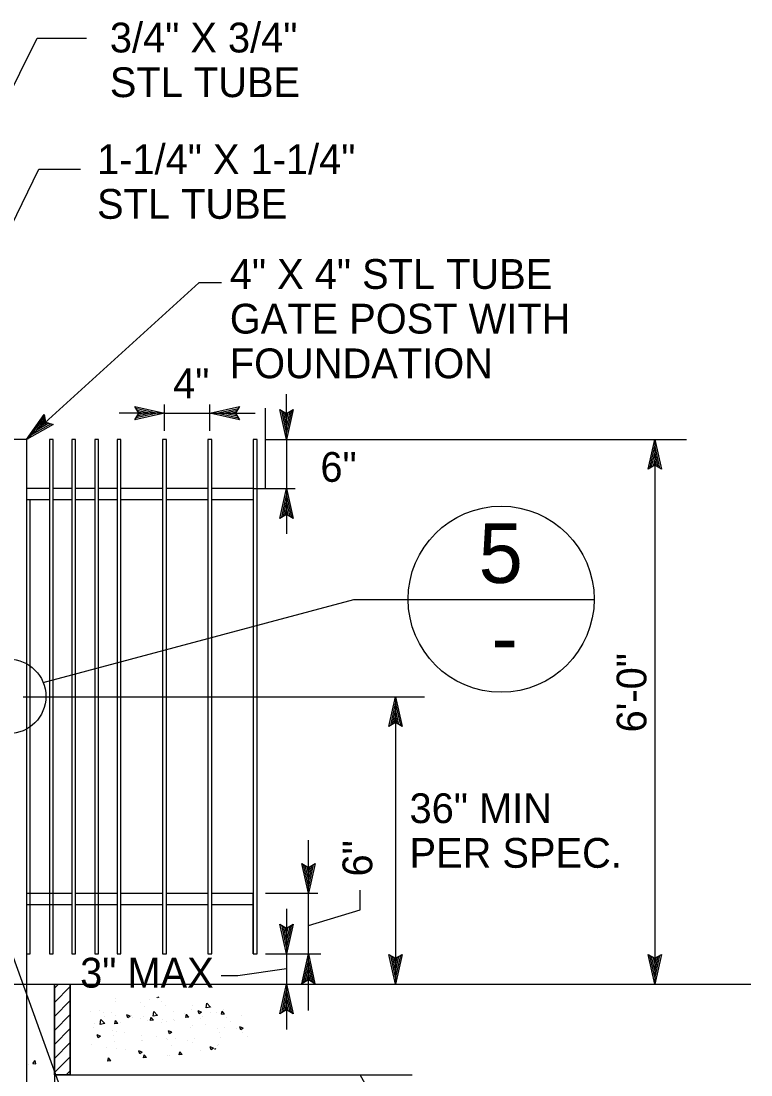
# Model space of a CAD drawing. Extents: x 6710407 to 6714861, y 1868090 to 1871317.
# Drawn here: x 6712218.2 to 6712365.4, y 1869755 to 1869967.3 of the extents above; entities that cross this region are included whole.
import ezdxf

# ---------------------------------------------------------------- set-up
doc = ezdxf.new("R2010")
doc.units = 0
for name, color, linetype in [('Erosion C (Lv35)', 7, 'Continuous'), ('G-MARK', 7, 'Continuous'), ('G-TEXT', 7, 'Continuous'), ('Nongeo Data(60)', 7, 'Continuous')]:
    doc.layers.add(name, color=color, linetype=linetype)

# ---------------------------------------------------------------- blocks, each defined once
blk = doc.blocks.new('SC8415')
at = {"layer": 'Erosion C (Lv35)'}
for p, q in [((-1.69662, 1.7688), (-1.69662, 1.7688)), ((-1.69606, 1.76963), (-1.69579, 1.76945)), ((-1.69579, 1.76945), (-1.69573, 1.76963)), ((-1.69408, 1.76913), (-1.69408, 1.76913)), ((-1.68715, 1.76926), (-1.68715, 1.76926)), ((-1.70955, 1.76614), (-1.70906, 1.76672)), ((-1.70943, 1.76711), (-1.70943, 1.76711)), ((-1.70894, 1.76609), (-1.70906, 1.76672)), ((-1.70689, 1.76745), (-1.70689, 1.76745)), ((-1.70669, 1.76754), (-1.7059, 1.76836)), ((-1.70669, 1.76754), (-1.70579, 1.7674)), ((-1.70579, 1.7674), (-1.7059, 1.76836)), ((-1.70484, 1.76651), (-1.70412, 1.76679)), ((-1.70433, 1.76617), (-1.70412, 1.76679)), ((-1.70304, 1.76795), (-1.70304, 1.76795)), ((-1.70278, 1.76714), (-1.70278, 1.76714)), ((-1.69901, 1.76659), (-1.69901, 1.76659)), ((-1.6975, 1.7679), (-1.6975, 1.7679)), ((-1.69585, 1.76586), (-1.69506, 1.76668)), ((-1.69494, 1.76572), (-1.69506, 1.76668)), ((-1.69309, 1.7676), (-1.69309, 1.7676)), ((-1.69228, 1.76861), (-1.69228, 1.76861)), ((-1.68716, 1.76862), (-1.68716, 1.76862)), ((-1.68394, 1.76681), (-1.68394, 1.76681)), ((-1.682, 1.76664), (-1.682, 1.76664)), ((-1.71312, 1.76577), (-1.71312, 1.76577)), ((-1.71086, 1.76455), (-1.71086, 1.76455)), ((-1.71, 1.76543), (-1.71, 1.76543)), ((-1.70955, 1.76614), (-1.70894, 1.76608)), ((-1.70791, 1.76649), (-1.70791, 1.76649)), ((-1.70672, 1.76656), (-1.70672, 1.76656)), ((-1.70494, 1.76557), (-1.70494, 1.76557)), ((-1.70484, 1.76651), (-1.70433, 1.76617)), ((-1.70458, 1.7652), (-1.70458, 1.7652)), ((-1.70226, 1.7655), (-1.70177, 1.76608)), ((-1.70226, 1.7655), (-1.70165, 1.76545)), ((-1.70165, 1.76545), (-1.70177, 1.76609)), ((-1.7013, 1.76633), (-1.7013, 1.76633)), ((-1.6993, 1.76479), (-1.6993, 1.76479)), ((-1.69916, 1.76497), (-1.69916, 1.76497)), ((-1.69762, 1.76452), (-1.69762, 1.76452)), ((-1.69675, 1.76513), (-1.69675, 1.76513)), ((-1.69588, 1.7661), (-1.69588, 1.7661)), ((-1.69585, 1.76586), (-1.69494, 1.76572)), ((-1.69497, 1.76486), (-1.69449, 1.76545)), ((-1.69497, 1.76486), (-1.69437, 1.76481)), ((-1.69437, 1.76481), (-1.69448, 1.76545)), ((-1.69373, 1.76474), (-1.69373, 1.76474)), ((-1.6929, 1.76563), (-1.6929, 1.76563)), ((-1.69241, 1.76523), (-1.69241, 1.76523)), ((-1.69065, 1.76537), (-1.69065, 1.76537)), ((-1.69045, 1.76587), (-1.69045, 1.76587)), ((-1.69023, 1.7657), (-1.68952, 1.76597)), ((-1.69023, 1.7657), (-1.68973, 1.76536)), ((-1.68973, 1.76536), (-1.68952, 1.76597)), ((-1.68831, 1.76451), (-1.68831, 1.76451)), ((-1.68769, 1.76423), (-1.6872, 1.76481)), ((-1.68727, 1.76588), (-1.68727, 1.76588)), ((-1.68708, 1.76417), (-1.6872, 1.76481)), ((-1.68649, 1.76648), (-1.68649, 1.76648)), ((-1.68503, 1.76565), (-1.68503, 1.76565)), ((-1.685, 1.76418), (-1.68421, 1.765)), ((-1.68473, 1.76639), (-1.68473, 1.76639)), ((-1.6841, 1.76404), (-1.68421, 1.765)), ((-1.71337, 1.76324), (-1.71266, 1.76351)), ((-1.71337, 1.76324), (-1.71287, 1.7629)), ((-1.71325, 1.76239), (-1.71325, 1.76239)), ((-1.71287, 1.7629), (-1.71266, 1.76351)), ((-1.7121, 1.7631), (-1.7121, 1.7631)), ((-1.70956, 1.76344), (-1.70956, 1.76344)), ((-1.70843, 1.76232), (-1.70843, 1.76232)), ((-1.70803, 1.7631), (-1.70803, 1.7631)), ((-1.70571, 1.76395), (-1.70571, 1.76395)), ((-1.7029, 1.76375), (-1.7029, 1.76375)), ((-1.7025, 1.76334), (-1.7025, 1.76334)), ((-1.69877, 1.76242), (-1.69806, 1.7627)), ((-1.69877, 1.76242), (-1.69827, 1.76208)), ((-1.69826, 1.76208), (-1.69806, 1.7627)), ((-1.69658, 1.76435), (-1.69658, 1.76435)), ((-1.68916, 1.76247), (-1.68916, 1.76247)), ((-1.68769, 1.76423), (-1.68708, 1.76417)), ((-1.6874, 1.7625), (-1.6874, 1.7625)), ((-1.68662, 1.7628), (-1.68662, 1.7628)), ((-1.685, 1.76418), (-1.6841, 1.76404)), ((-1.68289, 1.76428), (-1.68289, 1.76428)), ((-1.68277, 1.76331), (-1.68277, 1.76331)), ((-1.71417, 1.76163), (-1.71417, 1.76163)), ((-1.70874, 1.7614), (-1.70874, 1.7614)), ((-1.70332, 1.76117), (-1.70332, 1.76117)), ((-1.70302, 1.76037), (-1.70302, 1.76037)), ((-1.70197, 1.76078), (-1.70197, 1.76078)), ((-1.69943, 1.76112), (-1.69943, 1.76112)), ((-1.6979, 1.76094), (-1.6979, 1.76094)), ((-1.69775, 1.76113), (-1.69775, 1.76113)), ((-1.69558, 1.76162), (-1.69558, 1.76162)), ((-1.6927, 1.7608), (-1.6927, 1.7608)), ((-1.69253, 1.76185), (-1.69253, 1.76185)), ((-1.69247, 1.76071), (-1.69247, 1.76071)), ((-1.68705, 1.76048), (-1.68705, 1.76048)), ((-1.68677, 1.76182), (-1.68677, 1.76182)), ((-1.68417, 1.76161), (-1.68346, 1.76188)), ((-1.68417, 1.76161), (-1.68366, 1.76127)), ((-1.68366, 1.76127), (-1.68346, 1.76188)), ((-1.70839, 1.75994), (-1.70839, 1.75994)), ((-1.70815, 1.75972), (-1.70815, 1.75972)), ((-1.70775, 1.75896), (-1.70765, 1.75908)), ((-1.70762, 1.7589), (-1.70765, 1.75908)), ((-1.70731, 1.75915), (-1.7066, 1.75942)), ((-1.70731, 1.75915), (-1.7068, 1.75881)), ((-1.7068, 1.75881), (-1.7066, 1.75942)), ((-1.70455, 1.75876), (-1.70455, 1.75876)), ((-1.70085, 1.75786), (-1.70036, 1.75844)), ((-1.70024, 1.75781), (-1.70036, 1.75844)), ((-1.69862, 1.75978), (-1.69862, 1.75978)), ((-1.69271, 1.75833), (-1.692, 1.75861)), ((-1.69271, 1.75833), (-1.6922, 1.75799)), ((-1.69265, 1.75847), (-1.69265, 1.75847)), ((-1.6922, 1.75799), (-1.69199, 1.75861)), ((-1.69183, 1.75846), (-1.69183, 1.75846)), ((-1.68929, 1.7588), (-1.68929, 1.7588)), ((-1.68752, 1.75912), (-1.68752, 1.75912)), ((-1.68544, 1.7593), (-1.68544, 1.7593)), ((-1.68224, 1.75988), (-1.68224, 1.75988)), ((-1.70085, 1.75786), (-1.70025, 1.7578)), ((-1.69825, 1.75762), (-1.69825, 1.75762)), ((-1.69787, 1.75775), (-1.69787, 1.75775)), ((-1.69357, 1.75722), (-1.69308, 1.7578)), ((-1.69357, 1.75722), (-1.69296, 1.75717)), ((-1.69296, 1.75717), (-1.69307, 1.75781)), ((-1.68628, 1.75658), (-1.68579, 1.75717)), ((-1.68628, 1.75658), (-1.68567, 1.75653)), ((-1.68567, 1.75653), (-1.68579, 1.75717))]:
    blk.add_line(p, q, dxfattribs=at)

msp = doc.modelspace()

# ---------------------------------------------------------------- linework, layer by layer
at = {"layer": 'G-MARK'}
for p, q in [((6712221.51, 1869963.85), (6712231.4, 1869963.85)), ((6712221.81, 1869937.43), (6712230.24, 1869937.43)), ((6712271.76, 1869882.98), (6712271.76, 1869892.12)), ((6712247.15, 1869884.69), (6712247.15, 1869889.99)), ((6712256.29, 1869884.69), (6712256.29, 1869889.99)), ((6712247.15, 1869888.27), (6712238, 1869888.27)), ((6712247.15, 1869888.27), (6712256.29, 1869888.27)), ((6712256.29, 1869888.27), (6712265.43, 1869888.27)), ((6712267.53, 1869882.98), (6712352.35, 1869882.98)), ((6712267.53, 1869882.98), (6712273.48, 1869882.98)), ((6712271.76, 1869882.98), (6712271.76, 1869873.07)), ((6712345.98, 1869882.98), (6712345.98, 1869773.25)), ((6712271.76, 1869873.07), (6712271.76, 1869863.93)), ((6712222.72, 1869833.99), (6712285.31, 1869850.71)), ((6712285.31, 1869850.71), (6712296.07, 1869850.74)), ((6712218.67, 1869831.16), (6712299.57, 1869831.16)), ((6712293.73, 1869831.16), (6712293.73, 1869773.25)), ((6712234.89, 1869728.28), (6712198.51, 1869828.82)), ((6712276.16, 1869767.91), (6712276.16, 1869802.24)), ((6712286.57, 1869788.2), (6712286.57, 1869792.19)), ((6712267.53, 1869791.55), (6712278.05, 1869791.55)), ((6712271.76, 1869788.41), (6712271.76, 1869773.25)), ((6712276.16, 1869785.08), (6712286.57, 1869788.2)), ((6712267.53, 1869779.34), (6712278.68, 1869779.34)), ((6712271.76, 1869776.3), (6712261.95, 1869774.95)), ((6712261.95, 1869774.95), (6712258.56, 1869774.95)), ((6712271.76, 1869773.25), (6712271.76, 1869764.1)), ((6712292.64, 1869744.38), (6712286.57, 1869754.96))]:
    msp.add_line(p, q, dxfattribs=at)
for points in [[(6712179.33, 1869878.93), (6712221.51, 1869963.85), (6712221.51, 1869963.85)], [(6712190.63, 1869873.39), (6712221.81, 1869937.43)], [(6712258.62, 1869914.56), (6712254.1, 1869914.56), (6712219.34, 1869882.98)]]:
    msp.add_lwpolyline(points, dxfattribs=at)
at = {"layer": 'G-TEXT'}
for p, q in [((6712219.34, 1869882.98), (6712222.89, 1869888)), ((6712220.37, 1869883.92), (6712222.95, 1869887.58)), ((6712222.89, 1869888), (6712222.89, 1869888)), ((6712222.89, 1869888), (6712223.19, 1869886.48)), ((6712241.95, 1869888.27), (6712241.15, 1869889.61)), ((6712241.15, 1869889.61), (6712241.15, 1869889.61)), ((6712241.15, 1869889.61), (6712247.15, 1869888.27)), ((6712247.15, 1869888.27), (6712241.15, 1869886.94)), ((6712241.15, 1869886.94), (6712241.95, 1869888.27)), ((6712241.36, 1869889.25), (6712245.77, 1869888.27)), ((6712245.75, 1869888.27), (6712241.38, 1869887.3)), ((6712244.38, 1869888.27), (6712241.56, 1869887.65)), ((6712241.6, 1869888.9), (6712244.38, 1869888.27)), ((6712241.77, 1869888.55), (6712243, 1869888.27)), ((6712243, 1869888.27), (6712241.79, 1869888.01)), ((6712247.15, 1869888.27), (6712247.15, 1869888.27)), ((6712256.29, 1869888.27), (6712262.29, 1869889.6)), ((6712262.29, 1869886.93), (6712256.29, 1869888.27)), ((6712256.29, 1869888.27), (6712256.29, 1869888.27)), ((6712262.07, 1869887.29), (6712257.67, 1869888.27)), ((6712257.68, 1869888.27), (6712262.05, 1869889.24)), ((6712259.05, 1869888.27), (6712261.88, 1869888.89)), ((6712261.84, 1869887.65), (6712259.05, 1869888.27)), ((6712260.43, 1869888.27), (6712261.64, 1869888.54)), ((6712261.66, 1869887.99), (6712260.43, 1869888.27)), ((6712262.29, 1869889.6), (6712261.49, 1869888.27)), ((6712261.49, 1869888.27), (6712262.29, 1869886.93)), ((6712262.29, 1869889.6), (6712262.29, 1869889.6)), ((6712271.76, 1869882.98), (6712270.43, 1869888.98)), ((6712270.43, 1869888.98), (6712270.43, 1869888.98)), ((6712270.43, 1869888.98), (6712271.76, 1869888.18)), ((6712271.76, 1869884.37), (6712270.79, 1869888.74)), ((6712271.77, 1869885.74), (6712271.14, 1869888.56)), ((6712271.77, 1869887.12), (6712271.5, 1869888.33)), ((6712271.76, 1869888.18), (6712273.1, 1869888.98)), ((6712273.1, 1869888.98), (6712271.76, 1869882.98)), ((6712272.75, 1869888.76), (6712271.76, 1869884.35)), ((6712272.39, 1869888.52), (6712271.77, 1869885.74)), ((6712272.04, 1869888.35), (6712271.77, 1869887.12)), ((6712273.1, 1869888.98), (6712273.1, 1869888.98)), ((6712224.68, 1869886.02), (6712219.34, 1869882.98)), ((6712224.28, 1869886.14), (6712220.36, 1869883.91)), ((6712221.39, 1869884.84), (6712223.06, 1869887.2)), ((6712223.87, 1869886.25), (6712221.39, 1869884.84)), ((6712222.41, 1869885.77), (6712223.12, 1869886.78)), ((6712223.5, 1869886.39), (6712222.41, 1869885.77)), ((6712223.19, 1869886.48), (6712224.68, 1869886.02)), ((6712224.68, 1869886.02), (6712224.68, 1869886.02)), ((6712241.15, 1869886.94), (6712241.15, 1869886.94)), ((6712262.29, 1869886.93), (6712262.29, 1869886.93)), ((6712219.34, 1869882.98), (6712219.34, 1869882.98)), ((6712271.76, 1869882.98), (6712271.76, 1869882.98)), ((6712344.64, 1869876.98), (6712345.98, 1869882.98)), ((6712345, 1869877.19), (6712345.98, 1869881.6)), ((6712345.98, 1869882.98), (6712345.98, 1869882.98)), ((6712345.98, 1869882.98), (6712347.31, 1869876.97)), ((6712345.99, 1869881.58), (6712346.95, 1869877.21)), ((6712345.36, 1869877.43), (6712345.98, 1869880.21)), ((6712345.98, 1869880.21), (6712346.61, 1869877.39)), ((6712345.98, 1869877.78), (6712344.64, 1869876.98)), ((6712344.64, 1869876.98), (6712344.64, 1869876.98)), ((6712345.7, 1869877.6), (6712345.98, 1869878.83)), ((6712345.98, 1869878.83), (6712346.25, 1869877.62)), ((6712347.31, 1869876.98), (6712345.98, 1869877.78)), ((6712347.31, 1869876.98), (6712347.31, 1869876.98)), ((6712270.42, 1869867.07), (6712271.76, 1869873.07)), ((6712271.76, 1869873.07), (6712271.76, 1869873.07)), ((6712271.76, 1869873.07), (6712273.09, 1869867.07)), ((6712270.78, 1869867.29), (6712271.76, 1869871.69)), ((6712271.77, 1869871.68), (6712272.73, 1869867.3)), ((6712271.14, 1869867.52), (6712271.76, 1869870.31)), ((6712271.49, 1869867.7), (6712271.76, 1869868.92)), ((6712271.76, 1869870.31), (6712272.39, 1869867.48)), ((6712271.76, 1869868.92), (6712272.03, 1869867.72)), ((6712271.76, 1869867.87), (6712270.42, 1869867.07)), ((6712270.42, 1869867.07), (6712270.42, 1869867.07)), ((6712273.09, 1869867.07), (6712271.76, 1869867.87)), ((6712273.09, 1869867.07), (6712273.09, 1869867.07)), ((6712292.39, 1869825.16), (6712293.73, 1869831.16)), ((6712293.73, 1869831.16), (6712293.73, 1869831.16)), ((6712293.73, 1869831.16), (6712295.06, 1869825.16)), ((6712292.75, 1869825.38), (6712293.73, 1869829.78)), ((6712293.11, 1869825.61), (6712293.73, 1869828.4)), ((6712293.73, 1869829.77), (6712294.7, 1869825.39)), ((6712293.73, 1869828.4), (6712294.35, 1869825.57)), ((6712293.73, 1869825.96), (6712292.39, 1869825.16)), ((6712293.45, 1869825.79), (6712293.73, 1869827.01)), ((6712293.73, 1869827.01), (6712293.99, 1869825.81)), ((6712295.06, 1869825.16), (6712293.73, 1869825.96)), ((6712292.39, 1869825.16), (6712292.39, 1869825.16)), ((6712295.06, 1869825.16), (6712295.06, 1869825.16)), ((6712276.16, 1869791.55), (6712274.83, 1869797.55)), ((6712274.83, 1869797.55), (6712274.83, 1869797.55)), ((6712274.83, 1869797.55), (6712276.16, 1869796.75)), ((6712276.16, 1869792.94), (6712275.19, 1869797.32)), ((6712276.16, 1869794.32), (6712275.54, 1869797.14)), ((6712276.17, 1869795.7), (6712275.9, 1869796.91)), ((6712276.16, 1869796.75), (6712277.5, 1869797.55)), ((6712277.5, 1869797.55), (6712276.16, 1869791.55)), ((6712277.15, 1869797.34), (6712276.16, 1869792.93)), ((6712276.79, 1869797.1), (6712276.16, 1869794.32)), ((6712276.44, 1869796.93), (6712276.17, 1869795.7)), ((6712277.5, 1869797.55), (6712277.5, 1869797.55)), ((6712276.16, 1869791.55), (6712276.16, 1869791.55)), ((6712271.76, 1869779.34), (6712270.43, 1869785.34)), ((6712270.43, 1869785.34), (6712270.43, 1869785.34)), ((6712270.43, 1869785.34), (6712271.76, 1869784.54)), ((6712271.76, 1869780.73), (6712270.79, 1869785.11)), ((6712271.77, 1869782.11), (6712271.14, 1869784.93)), ((6712271.77, 1869783.49), (6712271.5, 1869784.7)), ((6712271.76, 1869784.54), (6712273.1, 1869785.34)), ((6712273.1, 1869785.34), (6712271.76, 1869779.34)), ((6712272.75, 1869785.13), (6712271.76, 1869780.72)), ((6712272.39, 1869784.89), (6712271.77, 1869782.11)), ((6712272.04, 1869784.72), (6712271.77, 1869783.49)), ((6712273.1, 1869785.34), (6712273.1, 1869785.34)), ((6712271.76, 1869779.34), (6712271.76, 1869779.34)), ((6712274.82, 1869773.34), (6712276.16, 1869779.34)), ((6712276.16, 1869779.34), (6712276.16, 1869779.34)), ((6712276.16, 1869779.34), (6712277.49, 1869773.34)), ((6712293.73, 1869773.25), (6712292.4, 1869779.25)), ((6712292.4, 1869779.25), (6712292.4, 1869779.25)), ((6712292.4, 1869779.25), (6712293.73, 1869778.45)), ((6712293.73, 1869778.45), (6712295.07, 1869779.25)), ((6712295.07, 1869779.25), (6712293.73, 1869773.25)), ((6712295.07, 1869779.25), (6712295.07, 1869779.25)), ((6712345.98, 1869773.25), (6712344.65, 1869779.25)), ((6712344.65, 1869779.25), (6712344.65, 1869779.25)), ((6712344.65, 1869779.25), (6712345.98, 1869778.45)), ((6712345.98, 1869778.45), (6712347.32, 1869779.25)), ((6712347.32, 1869779.25), (6712345.98, 1869773.25)), ((6712347.32, 1869779.25), (6712347.32, 1869779.25)), ((6712275.18, 1869773.56), (6712276.16, 1869777.96)), ((6712276.17, 1869777.95), (6712277.13, 1869773.58)), ((6712293.73, 1869774.64), (6712292.76, 1869779.01)), ((6712293.73, 1869776.01), (6712293.11, 1869778.83)), ((6712293.73, 1869777.39), (6712293.46, 1869778.6)), ((6712294.71, 1869779.03), (6712293.73, 1869774.63)), ((6712294.35, 1869778.8), (6712293.73, 1869776.01)), ((6712294.01, 1869778.62), (6712293.73, 1869777.39)), ((6712345.98, 1869774.64), (6712345.01, 1869779.01)), ((6712345.98, 1869776.01), (6712345.36, 1869778.83)), ((6712345.98, 1869777.39), (6712345.72, 1869778.6)), ((6712346.97, 1869779.03), (6712345.98, 1869774.63)), ((6712346.61, 1869778.8), (6712345.98, 1869776.01)), ((6712346.26, 1869778.62), (6712345.98, 1869777.39)), ((6712275.54, 1869773.79), (6712276.16, 1869776.58)), ((6712275.88, 1869773.97), (6712276.16, 1869775.2)), ((6712276.16, 1869776.58), (6712276.79, 1869773.76)), ((6712276.16, 1869775.2), (6712276.43, 1869773.99)), ((6712270.42, 1869767.25), (6712271.76, 1869773.25)), ((6712271.76, 1869773.25), (6712271.76, 1869773.25)), ((6712271.76, 1869773.25), (6712273.09, 1869767.25)), ((6712276.16, 1869774.14), (6712274.82, 1869773.34)), ((6712274.82, 1869773.34), (6712274.82, 1869773.34)), ((6712277.49, 1869773.34), (6712276.16, 1869774.14)), ((6712277.49, 1869773.34), (6712277.49, 1869773.34)), ((6712293.73, 1869773.25), (6712293.73, 1869773.25)), ((6712345.98, 1869773.25), (6712345.98, 1869773.25)), ((6712270.78, 1869767.46), (6712271.76, 1869771.87)), ((6712271.77, 1869771.86), (6712272.73, 1869767.48)), ((6712271.14, 1869767.7), (6712271.76, 1869770.48)), ((6712271.49, 1869767.87), (6712271.76, 1869769.1)), ((6712271.76, 1869770.48), (6712272.39, 1869767.66)), ((6712271.76, 1869769.1), (6712272.03, 1869767.89)), ((6712271.76, 1869768.05), (6712270.42, 1869767.25)), ((6712270.42, 1869767.25), (6712270.42, 1869767.25)), ((6712273.09, 1869767.25), (6712271.76, 1869768.05)), ((6712273.09, 1869767.25), (6712273.09, 1869767.25))]:
    msp.add_line(p, q, dxfattribs=at)
msp.add_lwpolyline([(6712219.34, 1869882.98), (6712219.33, 1869882.98), (6712219.34, 1869882.98)], close=True, dxfattribs=at)
at = {"layer": 'Nongeo Data(60)'}
for p, q in [((6712256.29, 1869888.27), (6712256.29, 1869888.27)), ((6712267.53, 1869873.07), (6712267.53, 1869889.25)), ((6712219.33, 1869882.98), (6712216.19, 1869882.98)), ((6712219.71, 1869882.98), (6712219.71, 1869882.98)), ((6712247.15, 1869882.98), (6712247.15, 1869882.98)), ((6712256.29, 1869882.98), (6712256.29, 1869882.98)), ((6712265.81, 1869882.98), (6712265.81, 1869882.98)), ((6712265.81, 1869874.78), (6712265.81, 1869874.78)), ((6712223.95, 1869873.07), (6712219.33, 1869873.07)), ((6712228.48, 1869873.07), (6712224.71, 1869873.07)), ((6712233.09, 1869873.07), (6712229.24, 1869873.07)), ((6712237.62, 1869873.07), (6712233.86, 1869873.07)), ((6712246.76, 1869873.07), (6712238.38, 1869873.07)), ((6712255.91, 1869873.07), (6712247.53, 1869873.07)), ((6712265.05, 1869873.07), (6712256.67, 1869873.07)), ((6712265.05, 1869873.07), (6712267.53, 1869873.07)), ((6712267.53, 1869873.07), (6712273.48, 1869873.07)), ((6712271.76, 1869873.07), (6712271.76, 1869873.07)), ((6712219.33, 1869870.78), (6712219.33, 1869729.74)), ((6712223.95, 1869870.78), (6712219.33, 1869870.78)), ((6712228.48, 1869870.78), (6712224.71, 1869870.78)), ((6712233.09, 1869870.78), (6712229.24, 1869870.78)), ((6712237.62, 1869870.78), (6712233.86, 1869870.78)), ((6712246.76, 1869870.78), (6712238.38, 1869870.78)), ((6712255.91, 1869870.78), (6712247.53, 1869870.78)), ((6712265.05, 1869870.78), (6712256.67, 1869870.78)), ((6712265.81, 1869868.69), (6712265.81, 1869868.69)), ((6712265.81, 1869868.69), (6712265.81, 1869868.69)), ((6712296.07, 1869850.74), (6712333.77, 1869850.74)), ((6712228.48, 1869791.54), (6712219.33, 1869791.54)), ((6712237.62, 1869791.54), (6712229.24, 1869791.54)), ((6712246.76, 1869791.54), (6712238.38, 1869791.54)), ((6712255.91, 1869791.54), (6712247.53, 1869791.54)), ((6712265.05, 1869791.54), (6712256.67, 1869791.54)), ((6712265.05, 1869779.34), (6712265.05, 1869791.54)), ((6712228.48, 1869789.25), (6712219.33, 1869789.25)), ((6712237.62, 1869789.25), (6712229.24, 1869789.25)), ((6712246.76, 1869789.25), (6712238.38, 1869789.25)), ((6712255.91, 1869789.25), (6712247.53, 1869789.25)), ((6712265.05, 1869789.25), (6712256.67, 1869789.25)), ((6712265.81, 1869779.34), (6712265.81, 1869779.34)), ((6712074.43, 1869773.25), (6712283.72, 1869773.25)), ((6712210.57, 1869773.25), (6712228.86, 1869773.25)), ((6712224.95, 1869773.25), (6712224.95, 1869736.67)), ((6712224.95, 1869772.41), (6712225.79, 1869773.25)), ((6712228.15, 1869754.96), (6712228.15, 1869773.25)), ((6712265.81, 1869773.25), (6712265.81, 1869773.25)), ((6712265.81, 1869773.25), (6712265.81, 1869773.25)), ((6712267.53, 1869773.25), (6712306.85, 1869773.25)), ((6712267.53, 1869773.25), (6712273.48, 1869773.25)), ((6712271.76, 1869773.25), (6712271.76, 1869773.25)), ((6712274.58, 1869773.25), (6712365.37, 1869773.25)), ((6712293.73, 1869773.25), (6712293.73, 1869773.25)), ((6712345.98, 1869773.25), (6712345.98, 1869773.25)), ((6712224.95, 1869769.58), (6712228.15, 1869772.77)), ((6712224.95, 1869766.75), (6712228.15, 1869769.95)), ((6712224.95, 1869763.92), (6712228.15, 1869767.12)), ((6712224.95, 1869761.1), (6712228.15, 1869764.29)), ((6712224.95, 1869758.27), (6712228.15, 1869761.46)), ((6712224.95, 1869755.44), (6712228.15, 1869758.63)), ((6712219.7, 1869757.06), (6712219.7, 1869757.06)), ((6712220.59, 1869757.26), (6712221.07, 1869757.84)), ((6712220.59, 1869757.26), (6712221.19, 1869757.21)), ((6712221.19, 1869757.21), (6712221.07, 1869757.84)), ((6712224.95, 1869754.96), (6712297.05, 1869754.96)), ((6712227.3, 1869754.96), (6712228.15, 1869755.8)), ((6712235.57, 1869754.96), (6712274.58, 1869754.96))]:
    msp.add_line(p, q, dxfattribs=at)
msp.add_lwpolyline([(6712219.33, 1869882.98), (6712219.33, 1869779.34), (6712220.09, 1869779.34), (6712220.09, 1869870.78)], dxfattribs=at)
for points in [[(6712223.95, 1869779.34), (6712224.71, 1869779.34), (6712224.71, 1869882.98), (6712223.95, 1869882.98)], [(6712228.48, 1869779.34), (6712229.24, 1869779.34), (6712229.24, 1869882.98), (6712228.48, 1869882.98)], [(6712233.09, 1869779.34), (6712233.86, 1869779.34), (6712233.86, 1869882.98), (6712233.09, 1869882.98)], [(6712237.62, 1869779.34), (6712238.38, 1869779.34), (6712238.38, 1869882.98), (6712237.62, 1869882.98)], [(6712246.76, 1869779.34), (6712247.53, 1869779.34), (6712247.53, 1869882.98), (6712246.76, 1869882.98)], [(6712255.91, 1869779.34), (6712256.67, 1869779.34), (6712256.67, 1869882.98), (6712255.91, 1869882.98)], [(6712265.05, 1869779.34), (6712265.81, 1869779.34), (6712265.81, 1869882.98), (6712265.05, 1869882.98)], [(6712224.95, 1869773.25), (6712228.15, 1869773.25), (6712228.15, 1869754.96), (6712224.95, 1869754.96)]]:
    msp.add_lwpolyline(points, close=True, dxfattribs=at)
for centre, radius in [((6712315.02, 1869850.79), 18.75), ((6712215.74, 1869831.22), 7.5)]:
    msp.add_circle(centre, radius, dxfattribs=at)

# ---------------------------------------------------------------- block references
at = {"layer": 'Nongeo Data(60)', "xscale": 984.251968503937, "yscale": -984.251968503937, "rotation": 180}
msp.add_blockref('SC8415', (6710576.63, 1868028.89), dxfattribs=at)

# ---------------------------------------------------------------- texts
at = {"layer": 'Nongeo Data(60)'}
for s, height, p in [('3/4" X 3/4"', 6, (6712236.14, 1869960.94)), ('STL TUBE', 6, (6712236.14, 1869951.94)), ('1-1/4" X 1-1/4"', 6, (6712233.56, 1869936.43)), ('STL TUBE', 6, (6712233.56, 1869927.43)), ('4" X 4" STL TUBE', 6, (6712260.32, 1869913.31)), ('GATE POST WITH', 6, (6712260.32, 1869904.31)), ('FOUNDATION', 6, (6712260.32, 1869895.31)), ('4"', 6, (6712248.89, 1869891.29)), ('6"', 6, (6712278.58, 1869874.44)), ('5', 12, (6712310.47, 1869854.07)), ('-', 12, (6712313.05, 1869837.12)), ('36" MIN', 6, (6712296.55, 1869805.69)), ('PER SPEC.', 6, (6712296.55, 1869796.69))]:
    msp.add_text(s, height=height, dxfattribs=at).set_placement(p)
for s, rotation, p in [('6\'-0"', 90, (6712344.3, 1869823.96)), ('6"', 90, (6712289.04, 1869794.93)), ('3" MAX', 360, (6712230.15, 1869772.55))]:
    msp.add_text(s, height=6, rotation=rotation, dxfattribs=at).set_placement(p)

doc.saveas('drawing.dxf')
